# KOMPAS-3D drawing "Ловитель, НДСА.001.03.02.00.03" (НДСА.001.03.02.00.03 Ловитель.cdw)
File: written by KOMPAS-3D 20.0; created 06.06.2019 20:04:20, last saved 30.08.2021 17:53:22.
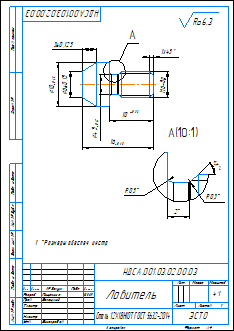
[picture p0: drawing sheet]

Sheet 1: A4, portrait

Document properties: Автор: Пользователь Windows; Параметр неуказанной шероховатости: Ra6.3; 150694406064: <item xmlns="http://appius.ru/pdm" xmlns:xs="http://www.w3.org/2001/XMLSchema" xmlns:xsi="http://www.w3.org/2001/XMLSchema-instance" xsi:type="item">  <element xmlns:d2p1="http://v8.1c.ru/8.1/data/enterprise/current-config" xsi:type="d2p1:CatalogRef.aps_Элемен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; Полное имя файла: НДСА.001.03.02.00.03 - Ловитель.m3d; 340649994805: <item xmlns="http://appius.ru/pdm" xmlns:xs="http://www.w3.org/2001/XMLSchema" xmlns:xsi="http://www.w3.org/2001/XMLSchema-instance" xsi:type="item">  <element xmlns:d2p1="http://v8.1c.ru/8.1/data/enterprise/current-config" xsi:type="d2p1:CatalogRef.aps_Элемен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; 291903931244: <item xmlns="http://appius.ru/pdm" xmlns:xs="http://www.w3.org/2001/XMLSchema" xmlns:xsi="http://www.w3.org/2001/XMLSchema-instance" xsi:type="item">  <element xmlns:d2p1="http://v8.1c.ru/8.1/data/enterprise/current-config" xsi:type="d2p1:CatalogRef.aps_Элемен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; 373644424540: <item xmlns="http://appius.ru/pdm" xmlns:xs="http://www.w3.org/2001/XMLSchema" xmlns:xsi="http://www.w3.org/2001/XMLSchema-instance" xsi:type="item">  <element xmlns:d2p1="http://v8.1c.ru/8.1/data/enterprise/current-config" xsi:type="d2p1:CatalogRef.aps_Элемен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; PLM_CDWXDTO: <item xmlns="http://appius.ru/pdm" xmlns:xs="http://www.w3.org/2001/XMLSchema" xmlns:xsi="http://www.w3.org/2001/XMLSchema-instance" xsi:type="item">  <element xmlns:d2p1="http://v8.1c.ru/8.1/data/enterprise/current-config" xsi:type="d2p1:CatalogRef.aps_Элемен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; 181403743429: <item xmlns="http://appius.ru/pdm" xmlns:xs="http://www.w3.org/2001/XMLSchema" xmlns:xsi="http://www.w3.org/2001/XMLSchema-instance" xsi:type="item">  <element xmlns:d2p1="http://v8.1c.ru/8.1/data/enterprise/current-config" xsi:type="d2p1:CatalogRef.aps_Элемен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; 181403743529: <item xmlns="http://appius.ru/pdm" xmlns:xs="http://www.w3.org/2001/XMLSchema" xmlns:xsi="http://www.w3.org/2001/XMLSchema-instance" xsi:type="item">  <element xmlns:d2p1="http://v8.1c.ru/8.1/data/enterprise/current-config" xsi:type="d2p1:CatalogRef.aps_Элемен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; 150694406164: <item xmlns="http://appius.ru/pdm" xmlns:xs="http://www.w3.org/2001/XMLSchema" xmlns:xsi="http://www.w3.org/2001/XMLSchema-instance" xsi:type="item">  <element xmlns:d2p1="http://v8.1c.ru/8.1/data/enterprise/current-config" xsi:type="d2p1:CatalogRef.aps_Элемен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; 356653799566: <item xmlns="http://appius.ru/pdm" xmlns:xs="http://www.w3.org/2001/XMLSchema" xmlns:xsi="http://www.w3.org/2001/XMLSchema-instance" xsi:type="item">  <element xmlns:d2p1="http://v8.1c.ru/8.1/data/enterprise/current-config" xsi:type="d2p1:CatalogRef.aps_Элемен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

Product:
- Part/product: Ловитель  | designation НДСА.001.03.02.00.03
    Материал: Сталь 12Х18Н10Т ГОСТ 5632-2014 (density 7900 kg/m3)
    Масса: 0.00501766
    additional columns: <item xmlns="http://appius.ru/pdm" xmlns:xs="http://www.w3.org/2001/XMLSchema" x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; <item xmlns="http://appius.ru/pdm" xmlns:xs="http://www.w3.org/2001/XMLSchema" x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; <item xmlns="http://appius.ru/pdm" xmlns:xs="http://www.w3.org/2001/XMLSchema" x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; <item xmlns="http://appius.ru/pdm" xmlns:xs="http://www.w3.org/2001/XMLSchema" x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; <item xmlns="http://appius.ru/pdm" xmlns:xs="http://www.w3.org/2001/XMLSchema" x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
    source file: НДСА.001.03.02.00.03 - Ловитель.cdw

Title block, sheet 1: Наименование: Ловитель; designation: НДСА.001.03.02.00.03; Материал: Сталь 12Х18Н10Т ГОСТ 5632-2014; Количество листов документа: 1; organisation: ЭСТО; Форматы листов документа: A4; stored path: C:\Users\Конструктор 3\Desktop\PLM\НДСА.001.03.02.00.03 - Ловитель.cdw; Разработал: Пищагина; Проверил: Белецкий; Утвердил: Виноградов; Разработал, date: 06.06.19

Views: Вид 1, Спереди, Выносной элемент 2, Выносной элемент А, Выносной элемент
Referenced files in C:\Users\Конструктор 3\Desktop\PLM\: НДСА.001.03.02.00.03 - Ловитель.m3d
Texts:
  Ra6.3
  НДСА.001.03.02.00.03 Ловитель
Dimensions and other numbers on the sheet: 6±0,15; 10; 4,5; -8g; 1; 3; 16; 0,5; 0,3; 2; 4:1; 06.06.19

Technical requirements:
  *Размеры обеспеч. инстр.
